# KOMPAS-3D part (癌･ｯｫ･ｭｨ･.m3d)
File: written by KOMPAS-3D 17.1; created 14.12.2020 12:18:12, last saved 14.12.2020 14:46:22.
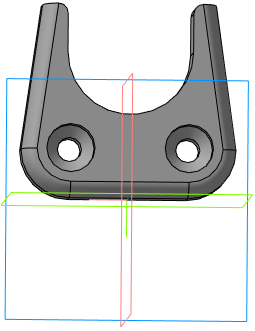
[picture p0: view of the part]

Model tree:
1. Эскиз:1
2. Элемент выдавливания:1
     Расстояние 1 = 15
3. Эскиз:2
4. Элемент выдавливания:2
     Расстояние 2 = 5
5. Фаска:1
     Угол = 45; Длина 1 = 2.5; Длина 2 = 2.5
6. Скругление:3
     Радиус = 2
7. Скругление:5
     Радиус = 1
8. Зеркальный массив:3
9. Экземпляр ( 1 )
10. Экземпляр ( 2 )  (with: Элемент выдавливания:1, Элемент выдавливания:2, Фаска:1, Скругление:3, Скругление:5)
11. Скругление:7
     Полуось 1 = 3; Полуось 2 = 8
